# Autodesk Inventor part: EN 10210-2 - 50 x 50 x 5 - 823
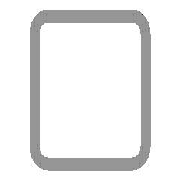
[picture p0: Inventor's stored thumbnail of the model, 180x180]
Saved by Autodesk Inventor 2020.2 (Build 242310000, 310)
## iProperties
_CCFamilyMember: 16
_CCFamilyDisplayName: DIN EN 10210-2 (USAS B17.1 quadratisch) - Rohrleitung — In Klammern angegebene Größen wurden aufgehoben
_FrameMemberDoc: Frame Member File
_Version: 15.0.0
_GetPNFromCC: 1
IsCustomPart: 1
Created: 2019-01
Part Number: EN 10210-2 - 50 x 50 x 5 - 823
Material: Stahl, weich
Description: Rohrleitung
Document SubType Name: Modeling
Standard: DIN
Designer: lutzd
Standard Revision: 2006-07
Standards Organization: DIN
Language: de-DE
Size Designation: 50 x 50 x 5
Categories: <MemberInstance><Categories><Category DisplayName="Profile" InternalName="089c4875-fa83-4c05-b084-43b9cc11f5ed" Mnemonic="GRDR"><CategoryParameter DisplayName="
Stock Number: 50 x 50 x 5
Mass: 5641.19 g
Surface Area: 2803.65 cm^2
Volume: 718.623 cm^3
Density: 7.85 g/cm^3
Appearance: Semi-Polished(8)
G_L: 823,000 mm
G_W: 50,000 mm
G_H: 50,000 mm
DocNumber: ADSK-014276
Folder: .
Dimensions: 50x50x823 mm
Mass: 5,641 kg
+7D4E7F53-A511-4BA1-99BA-82794B631833+SCHNITTDETAIL1: Schnittwinkel 90,00 grd
+C703460D-CF4A-4B31-BD9A-F4B54A2DDD3F+SCHNITTDETAIL2: Schnittwinkel 90,00 grd
VLT_Material: Stahl, weich
Title: Profil-Bauteil
Author: lutzd
Revision Number: -
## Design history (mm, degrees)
node "Startebene"
node "Endebene"
sketch "Skizze"
  geometry: L1 (-25, -17.5)-(-25, 17.5); L2 (-17.5, 25)-(17.5, 25); L3 (25, 17.5)-(25, -17.5); L4 (17.5, -25)-(-17.5, -25); L5 (-15, 20)-(15, 20); L6 (20, 15)-(20, -15); L7 (15, -20)-(-15, -20); L8 (-20, -15)-(-20, 15); L9 (0, 37.175)-(0, -37.175) reference; L10 (-37.175, 0)-(37.175, 0) reference; A1 r 7.5 centre (-17.5, -17.5) between (-25, -17.5) and (-17.5, -25); A2 r 7.5 centre (-17.5, 17.5) between (-17.5, 25) and (-25, 17.5); A3 r 7.5 centre (17.5, 17.5) between (25, 17.5) and (17.5, 25); A4 r 7.5 centre (17.5, -17.5) between (17.5, -25) and (25, -17.5); A5 r 5 centre (-15, -15) between (-20, -15) and (-15, -20); A6 r 5 centre (-15, 15) between (-15, 20) and (-20, 15); A7 r 5 centre (15, 15) between (20, 15) and (15, 20); A8 r 5 centre (15, -15) between (15, -20) and (20, -15)
  constraints: 16 end point, 16 point on circle, 16 tangent, 8 centre point, 6 equal radius, 4 parallel, 2 perpendicular, 2 other
  dimensions: "d7" = 7.5 radius of A1 (= G_IR); "d10" = 50 distance between parallel lines of L2 L4 (= G_H); "d11" = 50 distance between parallel lines of L1 L3 (= G_W); "d12" = 5 distance between parallel lines of L3 L6 (= G_T); "d15" = 25 distance between parallel lines of L2 L10 (= 0.5 x d10); "d16" = 25 distance between parallel lines of L9 L3 (= 0.5 x d11); "d19" = 5 radius of A5 (= G_T); "d20" = 5 distance between parallel lines of L4 L7 (= G_T)
extrude "Körper" new body sketch "Skizze" stored distance "d3" = 823 (= G_L); taper "d4" = 0 deg
node "Driven Length"
  sketch "Sketch3"
    geometry: L1 (0, 0)-(10, 0) reference
    constraints: 2 end point, 1 horizontal
  workplane "Work Plane3"
  sketch "Sketch4"
    geometry: L1 (-2, 35)-(12, 35) reference; L2 (-2, 858)-(12, 858) reference
    dimensions: "d18" = 823 distance between parallel lines of L1 L2 (derived)
workplane "Arbeitsebene4"
feature "Trennen1"
workplane "Arbeitsebene5"
feature "Trennen2"
body "Solid1"
other parameters: "G_W" = 50 [user parameter; used in 1 equation term], "G_H" = 50 [user parameter; used in 1 equation term], "G_T" = 5 [user parameter; used in 3 equation terms], "G_IR" = 7.5 [user parameter; used in 1 equation term], "G_L" = 823 (= d18) [user parameter; used in 1 equation term], "G_OFFSET_START" = -35 [user parameter; used in 1 equation term], "d13" = 35 (= -G_OFFSET_START), "d14" = 858 (= G_OFFSET_END + B_L), "B_L" = 908 [user parameter; used in 1 equation term], "d17" = 90 deg
